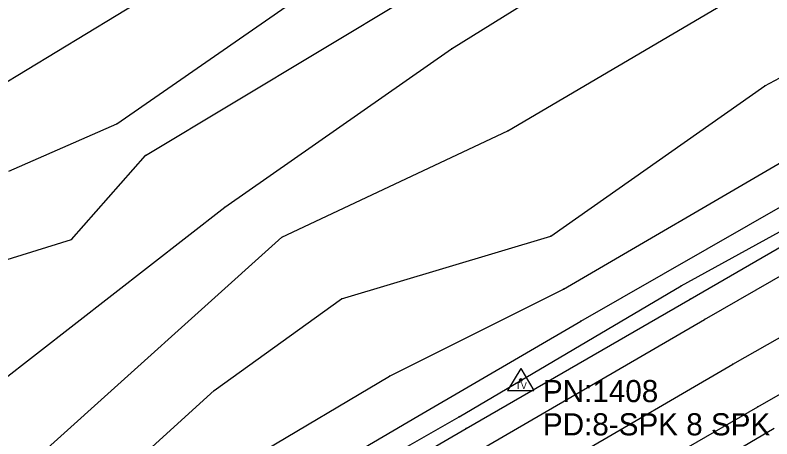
# Model space of a CAD drawing. Extents: x 1419505 to 1434054, y 1956910 to 1968644.
# Drawn here: x 1420936 to 1421106.8, y 1957814.5 to 1957910.2 of the extents above; entities that cross this region are included whole.
import ezdxf

# ---------------------------------------------------------------- set-up
doc = ezdxf.new("R2010")
doc.units = 0
for name, color, linetype in [('S_BREAKLINE', 7, 'Continuous'), ('S_DITCHLINE', 7, 'Continuous'), ('S_EDGE_PAVEMENT', 7, 'Continuous'), ('S_GRD_PT_SYM', 7, 'Continuous'), ('S_PAVEMENT_CROWN', 7, 'Continuous'), ('S_RDW_PT_SYM', 7, 'Continuous'), ('S_SECONDARY_CTL', 7, 'Continuous'), ('S_SECONDARY_CTL_ANNOT', 7, 'Continuous'), ('S_SHOULDER', 7, 'Continuous')]:
    doc.layers.add(name, color=color, linetype=linetype)

msp = doc.modelspace()

# ---------------------------------------------------------------- linework, layer by layer
at = {"layer": 'S_BREAKLINE'}
for p, q in [((1420931.3763, 1957893.4698), (1421020.6221, 1957947.7293)), ((1421034.475, 1957902.5604), (1421087.7344, 1957935.7455)), ((1420965.4495, 1957878.5298), (1421025.9994, 1957914.9372)), ((1421047.2158, 1957884.0522), (1421096.865, 1957913.2501)), ((1421105.1966, 1957894.1948), (1421137.7217, 1957911.774)), ((1420983.3807, 1957866.8421), (1421034.475, 1957902.5604)), ((1421056.8834, 1957860.3027), (1421105.1966, 1957894.1948)), ((1420996.2305, 1957860.0436), (1421047.2158, 1957884.0522)), ((1421059.7326, 1957848.3269), (1421113.5671, 1957879.7639)), ((1420948.7224, 1957859.5456), (1420965.4495, 1957878.5298)), ((1421086.3023, 1957849.0519), (1421137.8427, 1957877.4388)), ((1421063.6789, 1957841.1344), (1421117.9964, 1957872.2334)), ((1420932.2634, 1957827.0765), (1420983.3807, 1957866.8421)), ((1420881.8621, 1957838.7443), (1420948.7224, 1957859.5456)), ((1420942.6081, 1957811.7415), (1420996.2305, 1957860.0436)), ((1421009.6744, 1957846.1207), (1421056.8834, 1957860.3027)), ((1421036.2031, 1957819.514), (1421086.3023, 1957849.0519)), ((1421020.4851, 1957828.6486), (1421059.7326, 1957848.3269)), ((1420980.9665, 1957825.4484), (1421009.6744, 1957846.1207)), ((1421026.9175, 1957819.634), (1421063.6789, 1957841.1344)), ((1420990.3051, 1957810.7585), (1421020.4851, 1957828.6486)), ((1420950.2195, 1957797.5756), (1420980.9665, 1957825.4484)), ((1420983.8527, 1957789.5811), (1421036.2031, 1957819.514)), ((1420996.5485, 1957801.9179), (1421026.9175, 1957819.634))]:
    msp.add_line(p, q, dxfattribs=at)
at = {"layer": 'S_DITCHLINE'}
for p, q in [((1420958.9941, 1957885.6413), (1421022.7682, 1957929.9342)), ((1420934.6225, 1957874.9346), (1420958.9941, 1957885.6413))]:
    msp.add_line(p, q, dxfattribs=at)
at = {"layer": 'S_EDGE_PAVEMENT'}
for p, q in [((1421091.5807, 1957841.4614), (1421141.7479, 1957870.3513)), ((1421103.5864, 1957821.7922), (1421152.6866, 1957849.768)), ((1421040.5654, 1957811.7935), (1421091.5807, 1957841.4614)), ((1421050.219, 1957790.9132), (1421103.5864, 1957821.7922))]:
    msp.add_line(p, q, dxfattribs=at)
at = {"layer": 'S_GRD_PT_SYM'}
for points in [[(1421034.475, 1957902.5604), (1421034.475, 1957902.6104), (1421034.475, 1957902.5604), (1421034.425, 1957902.5604), (1421034.475, 1957902.5604), (1421034.475, 1957902.5104), (1421034.475, 1957902.5604), (1421034.525, 1957902.5604)], [(1421105.1966, 1957894.1948), (1421105.1966, 1957894.2448), (1421105.1966, 1957894.1948), (1421105.1466, 1957894.1948), (1421105.1966, 1957894.1948), (1421105.1966, 1957894.1448), (1421105.1966, 1957894.1948), (1421105.2466, 1957894.1948)], [(1420958.9941, 1957885.6413), (1420958.9941, 1957885.6913), (1420958.9941, 1957885.6413), (1420958.9441, 1957885.6413), (1420958.9941, 1957885.6413), (1420958.9941, 1957885.5913), (1420958.9941, 1957885.6413), (1420959.0441, 1957885.6413)], [(1421047.2158, 1957884.0522), (1421047.2158, 1957884.1022), (1421047.2158, 1957884.0522), (1421047.1658, 1957884.0522), (1421047.2158, 1957884.0522), (1421047.2158, 1957884.0022), (1421047.2158, 1957884.0522), (1421047.2658, 1957884.0522)], [(1420965.4495, 1957878.5298), (1420965.4495, 1957878.5798), (1420965.4495, 1957878.5298), (1420965.3995, 1957878.5298), (1420965.4495, 1957878.5298), (1420965.4495, 1957878.4798), (1420965.4495, 1957878.5298), (1420965.4995, 1957878.5298)], [(1420983.3807, 1957866.8421), (1420983.3807, 1957866.8921), (1420983.3807, 1957866.8421), (1420983.3307, 1957866.8421), (1420983.3807, 1957866.8421), (1420983.3807, 1957866.7921), (1420983.3807, 1957866.8421), (1420983.4307, 1957866.8421)], [(1420948.7224, 1957859.5456), (1420948.7224, 1957859.5956), (1420948.7224, 1957859.5456), (1420948.6724, 1957859.5456), (1420948.7224, 1957859.5456), (1420948.7224, 1957859.4956), (1420948.7224, 1957859.5456), (1420948.7724, 1957859.5456)], [(1420996.2305, 1957860.0436), (1420996.2305, 1957860.0936), (1420996.2305, 1957860.0436), (1420996.1805, 1957860.0436), (1420996.2305, 1957860.0436), (1420996.2305, 1957859.9936), (1420996.2305, 1957860.0436), (1420996.2805, 1957860.0436)], [(1421056.8834, 1957860.3027), (1421056.8834, 1957860.3527), (1421056.8834, 1957860.3027), (1421056.8334, 1957860.3027), (1421056.8834, 1957860.3027), (1421056.8834, 1957860.2527), (1421056.8834, 1957860.3027), (1421056.9334, 1957860.3027)], [(1421086.3023, 1957849.0519), (1421086.3023, 1957849.1019), (1421086.3023, 1957849.0519), (1421086.2523, 1957849.0519), (1421086.3023, 1957849.0519), (1421086.3023, 1957849.0019), (1421086.3023, 1957849.0519), (1421086.3523, 1957849.0519)], [(1421059.7326, 1957848.3269), (1421059.7326, 1957848.3769), (1421059.7326, 1957848.3269), (1421059.6826, 1957848.3269), (1421059.7326, 1957848.3269), (1421059.7326, 1957848.2769), (1421059.7326, 1957848.3269), (1421059.7826, 1957848.3269)], [(1421009.6744, 1957846.1207), (1421009.6744, 1957846.1707), (1421009.6744, 1957846.1207), (1421009.6244, 1957846.1207), (1421009.6744, 1957846.1207), (1421009.6744, 1957846.0707), (1421009.6744, 1957846.1207), (1421009.7244, 1957846.1207)], [(1421063.6789, 1957841.1344), (1421063.6789, 1957841.1844), (1421063.6789, 1957841.1344), (1421063.6289, 1957841.1344), (1421063.6789, 1957841.1344), (1421063.6789, 1957841.0844), (1421063.6789, 1957841.1344), (1421063.7289, 1957841.1344)], [(1421020.4851, 1957828.6486), (1421020.4851, 1957828.6986), (1421020.4851, 1957828.6486), (1421020.4351, 1957828.6486), (1421020.4851, 1957828.6486), (1421020.4851, 1957828.5986), (1421020.4851, 1957828.6486), (1421020.5351, 1957828.6486)], [(1420980.9665, 1957825.4484), (1420980.9665, 1957825.4984), (1420980.9665, 1957825.4484), (1420980.9165, 1957825.4484), (1420980.9665, 1957825.4484), (1420980.9665, 1957825.3984), (1420980.9665, 1957825.4484), (1420981.0165, 1957825.4484)], [(1421026.9175, 1957819.634), (1421026.9175, 1957819.684), (1421026.9175, 1957819.634), (1421026.8675, 1957819.634), (1421026.9175, 1957819.634), (1421026.9175, 1957819.584), (1421026.9175, 1957819.634), (1421026.9675, 1957819.634)], [(1421036.2031, 1957819.514), (1421036.2031, 1957819.564), (1421036.2031, 1957819.514), (1421036.1531, 1957819.514), (1421036.2031, 1957819.514), (1421036.2031, 1957819.464), (1421036.2031, 1957819.514), (1421036.2531, 1957819.514)]]:
    msp.add_lwpolyline(points, dxfattribs=at)
at = {"layer": 'S_PAVEMENT_CROWN'}
for p, q in [((1421097.9831, 1957831.3948), (1421147.5823, 1957859.7536)), ((1421045.6937, 1957800.9508), (1421097.9831, 1957831.3948))]:
    msp.add_line(p, q, dxfattribs=at)
at = {"layer": 'S_RDW_PT_SYM'}
for points in [[(1421088.3435, 1957846.0517), (1421088.3435, 1957846.1017), (1421088.3435, 1957846.0517), (1421088.2935, 1957846.0517), (1421088.3435, 1957846.0517), (1421088.3435, 1957846.0017), (1421088.3435, 1957846.0517), (1421088.3935, 1957846.0517)], [(1421091.5807, 1957841.4614), (1421091.5807, 1957841.5114), (1421091.5807, 1957841.4614), (1421091.5307, 1957841.4614), (1421091.5807, 1957841.4614), (1421091.5807, 1957841.4114), (1421091.5807, 1957841.4614), (1421091.6307, 1957841.4614)], [(1421097.9831, 1957831.3948), (1421097.9831, 1957831.4448), (1421097.9831, 1957831.3948), (1421097.9331, 1957831.3948), (1421097.9831, 1957831.3948), (1421097.9831, 1957831.3448), (1421097.9831, 1957831.3948), (1421098.0331, 1957831.3948)], [(1421103.5864, 1957821.7922), (1421103.5864, 1957821.8422), (1421103.5864, 1957821.7922), (1421103.5364, 1957821.7922), (1421103.5864, 1957821.7922), (1421103.5864, 1957821.7422), (1421103.5864, 1957821.7922), (1421103.6364, 1957821.7922)], [(1421037.7742, 1957816.8639), (1421037.7742, 1957816.9139), (1421037.7742, 1957816.8639), (1421037.7242, 1957816.8639), (1421037.7742, 1957816.8639), (1421037.7742, 1957816.8139), (1421037.7742, 1957816.8639), (1421037.8242, 1957816.8639)]]:
    msp.add_lwpolyline(points, dxfattribs=at)
at = {"layer": 'S_SECONDARY_CTL'}
for p, q in [((1421050.13, 1957830.4227), (1421047.12, 1957825.4688)), ((1421050.13, 1957830.4227), (1421053.0773, 1957825.4688)), ((1421047.12, 1957825.4688), (1421053.0773, 1957825.4688))]:
    msp.add_line(p, q, dxfattribs=at)
for radius in [0.3111, 0.1827, 0.1033]:
    msp.add_circle((1421050.13, 1957827.8126), radius, dxfattribs=at)
at = {"layer": 'S_SHOULDER'}
for p, q in [((1421088.3435, 1957846.0517), (1421138.9837, 1957875.3796)), ((1421037.7742, 1957816.8639), (1421088.3435, 1957846.0517)), ((1420985.4668, 1957786.4499), (1421037.7742, 1957816.8639)), ((1421052.2721, 1957784.7058), (1421107.2787, 1957816.9229))]:
    msp.add_line(p, q, dxfattribs=at)

# ---------------------------------------------------------------- texts
at = {"layer": 'S_SECONDARY_CTL'}
msp.add_text('TV', height=1.5, rotation=360, dxfattribs=at).set_placement((1421048.9253, 1957825.8013))
at = {"layer": 'S_SECONDARY_CTL_ANNOT'}
for s, p in [('PN:1408', (1421055.13, 1957822.8126)), ('PD:8-SPK 8 SPK', (1421055.13, 1957815.3126))]:
    msp.add_text(s, height=5, dxfattribs=at).set_placement(p)

doc.saveas('drawing.dxf')
